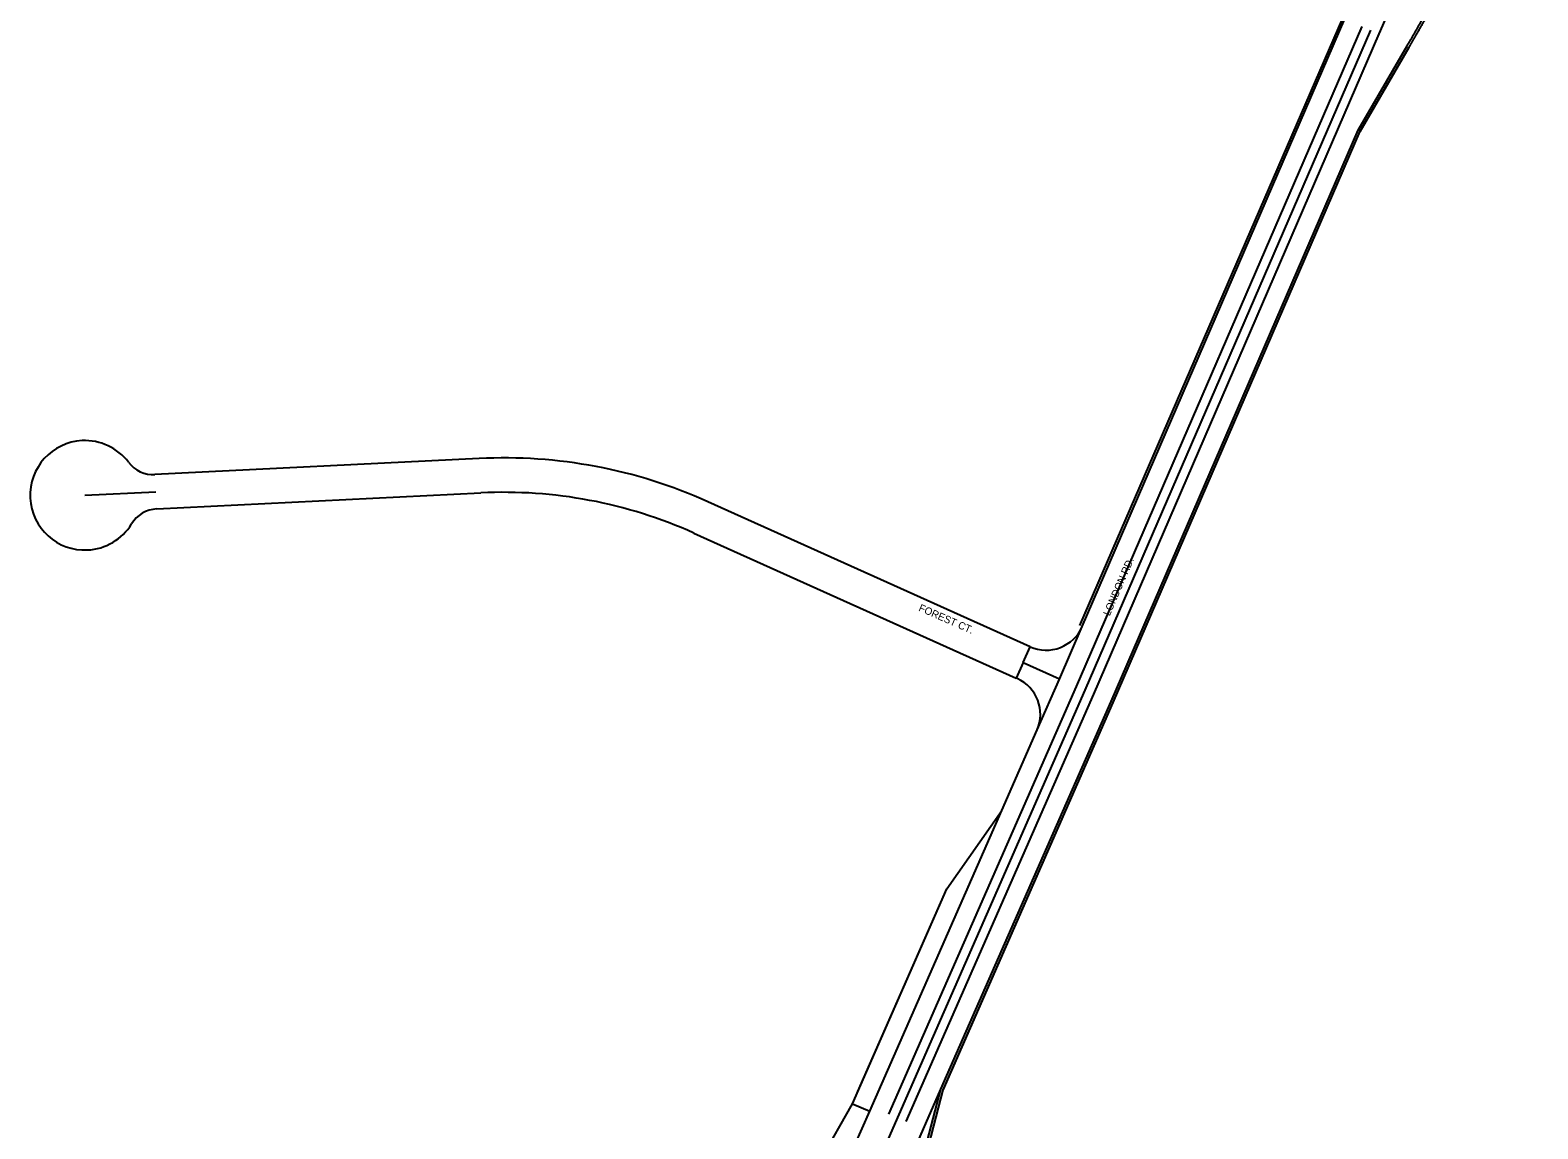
# Model space of a CAD drawing. Extents: x 2315515 to 2326910, y 758186 to 762794.
# Drawn here: x 2320679 to 2321643, y 760752 to 761455 of the extents above; entities that cross this region are included whole.
import ezdxf

# ---------------------------------------------------------------- set-up
doc = ezdxf.new("R2010")
doc.units = 0
for name, color, linetype in [('Default', 7, 'Continuous'), ('Draft_Corr_Range_Design', 7, 'Continuous'), ('E_Terrain_Exterior', 7, 'Continuous'), ('Level 0', 7, 'Continuous'), ('Pavement Marking Yellow', 7, 'Continuous'), ('Road_Curb_Face', 7, 'Continuous'), ('TL_End Condition Ditch In', 7, 'Continuous'), ('TL_End Condition Ditch Out', 7, 'Continuous')]:
    doc.layers.add(name, color=color, linetype=linetype)

msp = doc.modelspace()

# ---------------------------------------------------------------- linework, layer by layer
at = {"layer": 'Default'}
for p, q in [((2321353.37, 761032.31), (2321535.94, 761454.53)), ((2321353.37, 761032.31), (2321535.94, 761454.53)), ((2321353.37, 761032.31), (2321535.94, 761454.53)), ((2320896.62, 759992.18), (2321353.37, 761032.31)), ((2320896.62, 759992.18), (2321353.37, 761032.31)), ((2320896.62, 759992.18), (2321353.37, 761032.31))]:
    msp.add_line(p, q, dxfattribs=at)
at = {"layer": 'Draft_Corr_Range_Design'}
msp.add_line((2321215.5, 760763.1), (2321299.94, 760955.41), dxfattribs=at)
at = {"layer": 'E_Terrain_Exterior'}
for p, q in [((2321351.39, 761073.08), (2321519.42, 761461.68)), ((2321351.39, 761073.08), (2321519.42, 761461.68)), ((2321527.89, 761390.58), (2321559.28, 761444.44)), ((2321527.89, 761390.58), (2321559.28, 761444.44)), ((2321369.88, 761025.12), (2321527.89, 761390.58)), ((2321369.88, 761025.12), (2321527.89, 761390.58)), ((2320965.75, 761180.56), (2320758.41, 761170.26)), ((2320965.75, 761180.56), (2320758.41, 761170.26)), ((2320759.5, 761148.29), (2320966.84, 761158.59)), ((2321318.19, 761060.2), (2321111.97, 761152.96)), ((2321318.19, 761060.2), (2321111.97, 761152.96)), ((2321102.95, 761132.9), (2321309.16, 761040.14)), ((2321313.68, 761050.17), (2321318.19, 761060.2)), ((2321313.68, 761050.17), (2321309.16, 761040.14)), ((2321309.94, 761039.79), (2321309.16, 761040.14)), ((2321261.03, 760777.26), (2321369.88, 761025.12)), ((2321261.03, 760777.26), (2321369.88, 761025.12)), ((2321299.94, 760955.41), (2321322.57, 761006.94)), ((2321299.94, 760955.41), (2321322.57, 761006.94)), ((2321264.83, 760905.3), (2321299.94, 760955.41)), ((2321204.51, 760767.93), (2321264.83, 760905.3)), ((2321207.9, 760775.65), (2321264.83, 760905.3)), ((2321248.25, 760728.26), (2321261.03, 760777.26)), ((2321184.77, 760732.91), (2321204.51, 760767.93))]:
    msp.add_line(p, q, dxfattribs=at)
for centre, radius, start, end in [((2320713.58, 761157.03), 35, 92.84252, 272.84252), ((2320713.58, 761157.03), 35, 37.15017, 92.84252), ((2320757.42, 761190.24), 20, 217.15017, 272.84252), ((2320757.42, 761190.24), 20, 217.15017, 272.84252), ((2320981.52, 760862.95), 318, 65.781, 92.84252), ((2320981.52, 760862.95), 318, 65.781, 92.84252), ((2320981.52, 760862.95), 296, 65.781, 92.84252), ((2320760.49, 761128.32), 20, 92.84252, 148.53487), ((2320760.49, 761128.32), 20, 92.84252, 148.53487), ((2320713.58, 761157.03), 35, 272.84252, 328.53487), ((2321328.44, 761083), 25, 245.781, 336.61697), ((2321299.68, 761016.99), 25, 336.2923, 65.781), ((2321299.68, 761016.99), 25, 336.2923, 65.781)]:
    msp.add_arc(centre, radius, start, end, dxfattribs=at)
msp.add_open_spline([(2321559.28, 761444.44), (2321559.6, 761445), (2321560.25, 761446.12), (2321561.22, 761447.8), (2321562.2, 761449.48), (2321563.17, 761451.17), (2321564.13, 761452.85), (2321565.1, 761454.54), (2321566.07, 761456.22), (2321567.03, 761457.91), (2321567.99, 761459.6), (2321568.96, 761461.29), (2321569.92, 761462.98), (2321570.87, 761464.67), (2321571.83, 761466.36), (2321572.79, 761468.05), (2321573.74, 761469.75), (2321574.69, 761471.44), (2321575.64, 761473.14), (2321576.59, 761474.84), (2321577.54, 761476.54), (2321578.17, 761477.67), (2321578.49, 761478.24)], degree=3, dxfattribs=at)
msp.add_open_spline([(2321559.28, 761444.44), (2321559.6, 761445), (2321560.25, 761446.12), (2321561.22, 761447.8), (2321562.2, 761449.48), (2321563.17, 761451.17), (2321564.13, 761452.85), (2321565.1, 761454.54), (2321566.07, 761456.22), (2321567.03, 761457.91), (2321567.99, 761459.6), (2321568.96, 761461.29), (2321569.92, 761462.98), (2321570.87, 761464.67), (2321571.83, 761466.36), (2321572.79, 761468.05), (2321573.74, 761469.75), (2321574.69, 761471.44), (2321575.64, 761473.14), (2321576.59, 761474.84), (2321577.54, 761476.54), (2321578.17, 761477.67), (2321578.49, 761478.24)], degree=3, dxfattribs=at)
at = {"layer": 'Level 0'}
msp.add_line((2320713.58, 761157.03), (2320713.58, 761157.03), dxfattribs=at)
at = {"layer": 'Pavement Marking Yellow'}
for p, q in [((2321347.87, 761034.71), (2321530.43, 761456.92)), ((2321358.88, 761029.92), (2321541.44, 761452.15)), ((2321227.78, 760761.22), (2321347.87, 761034.71)), ((2321238.83, 760756.54), (2321358.88, 761029.92))]:
    msp.add_line(p, q, dxfattribs=at)
msp.add_arc((2319608.41, 762287.97), 2106, 336.61697, 345.02036, dxfattribs=at)
at = {"layer": 'Road_Curb_Face'}
for p, q in [((2321350.01, 761073.67), (2321518.04, 761462.27)), ((2321529.19, 761389.82), (2321560.57, 761443.69)), ((2321529.23, 761389.9), (2321560.57, 761443.69)), ((2321371.25, 761024.52), (2321529.27, 761389.98)), ((2321371.25, 761024.52), (2321529.23, 761389.9)), ((2321262.41, 760776.66), (2321371.25, 761024.52)), ((2321262.45, 760776.76), (2321371.25, 761024.52)), ((2321249.7, 760727.88), (2321262.48, 760776.88)), ((2321249.7, 760727.88), (2321262.45, 760776.76))]:
    msp.add_line(p, q, dxfattribs=at)
msp.add_open_spline([(2321560.57, 761443.69), (2321560.76, 761444.01), (2321561.4, 761445.11), (2321562.57, 761447.12), (2321563.49, 761448.72), (2321564.47, 761450.43), (2321565.44, 761452.11), (2321566.41, 761453.8), (2321567.37, 761455.49), (2321568.34, 761457.17), (2321569.3, 761458.86), (2321570.27, 761460.55), (2321571.23, 761462.25), (2321572.18, 761463.94), (2321573.14, 761465.63), (2321574.1, 761467.32), (2321575.05, 761469.02), (2321576, 761470.71), (2321576.97, 761472.43), (2321577.87, 761474.04), (2321579, 761476.07), (2321579.62, 761477.19), (2321579.8, 761477.51)], degree=2, dxfattribs=at)
msp.add_open_spline([(2321560.57, 761443.69), (2321560.76, 761444.01), (2321561.4, 761445.11), (2321562.57, 761447.12), (2321563.49, 761448.72), (2321564.47, 761450.43), (2321565.44, 761452.11), (2321566.41, 761453.8), (2321567.37, 761455.49), (2321568.34, 761457.17), (2321569.3, 761458.86), (2321570.27, 761460.55), (2321571.23, 761462.25), (2321572.18, 761463.94), (2321573.14, 761465.63), (2321574.1, 761467.32), (2321575.05, 761469.02), (2321576, 761470.71), (2321576.97, 761472.43), (2321577.87, 761474.04), (2321579, 761476.07), (2321579.62, 761477.19), (2321579.8, 761477.51)], degree=2, dxfattribs=at)
at = {"layer": 'TL_End Condition Ditch In'}
for p, q in [((2321336.87, 761039.5), (2321351.39, 761073.08)), ((2321313.68, 761050.17), (2321336.96, 761039.7)), ((2321322.57, 761006.94), (2321336.87, 761039.5)), ((2321196.22, 760629.68), (2321261.03, 760777.26)), ((2321204.51, 760767.93), (2321215.5, 760763.1)), ((2321162.98, 760643.51), (2321215.5, 760763.1))]:
    msp.add_line(p, q, dxfattribs=at)
at = {"layer": 'TL_End Condition Ditch Out'}
msp.add_line((2320713.58, 761157.03), (2320758.95, 761159.28), dxfattribs=at)

# ---------------------------------------------------------------- texts
at = {"layer": 'Default'}
for s, rotation, p in [('LONDON RD.', 66.74652, (2321368.99, 761079.54)), ('FOREST CT.', 336.32168, (2321246.41, 761083.34))]:
    msp.add_text(s, height=4.724, rotation=rotation, dxfattribs=at).set_placement(p)

doc.saveas('drawing.dxf')
